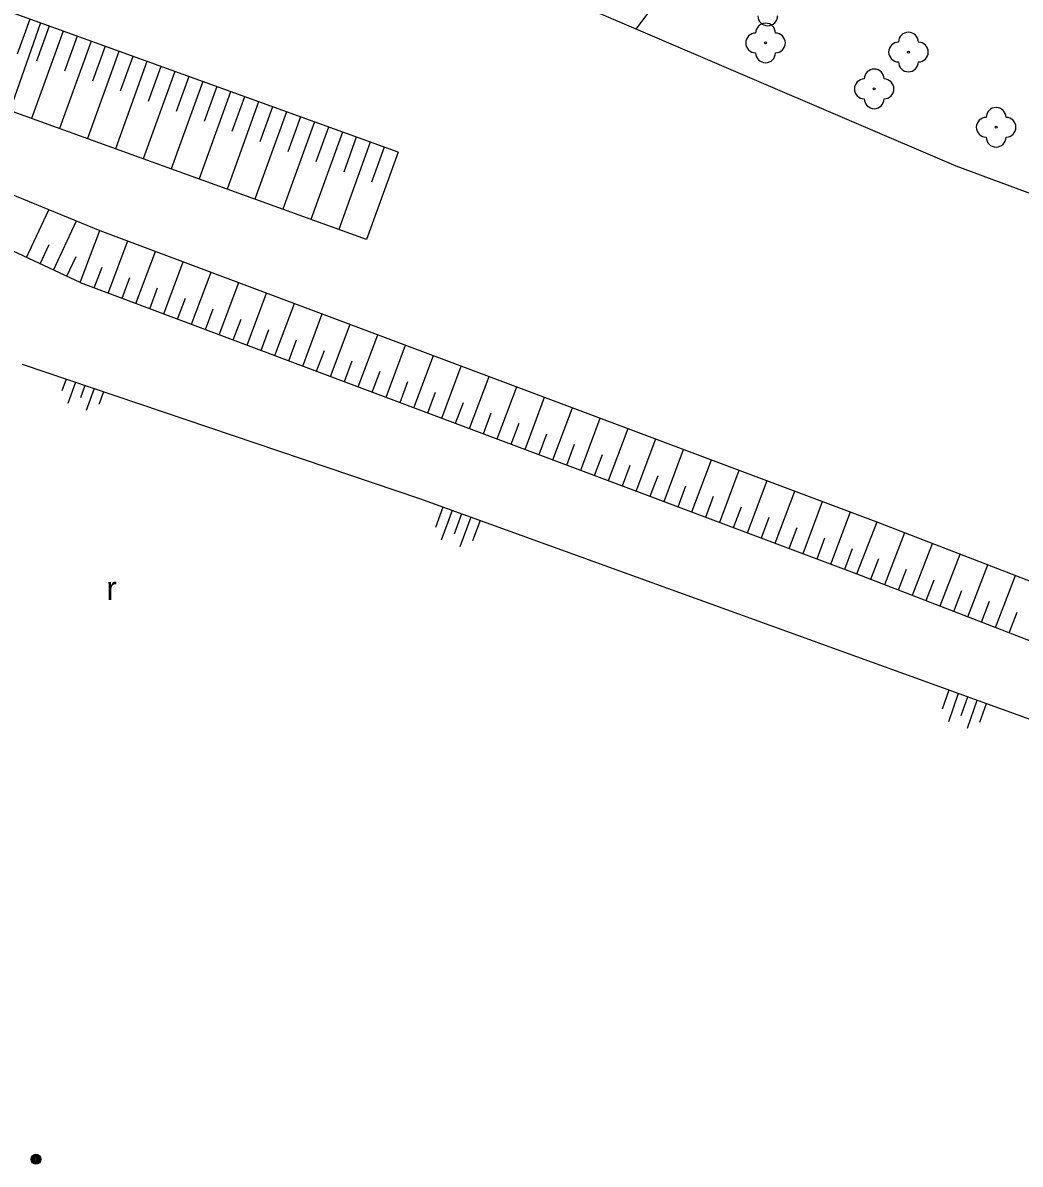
# Model space of a CAD drawing. Extents: x -539515 to -538098, y -1182060 to -1180157.
# Drawn here: x -538751.7 to -538701.3, y -1181681.4 to -1181623.8 of the extents above; entities that cross this region are included whole.
import ezdxf

# ---------------------------------------------------------------- set-up
doc = ezdxf.new("R2010")
doc.units = 0
for name, color, linetype in [('Vrstva 10', 7, 'Continuous'), ('Vrstva 14', 7, 'Continuous'), ('Vrstva 15', 7, 'Continuous'), ('Vrstva 21', 7, 'Continuous'), ('Vrstva 22', 7, 'Continuous'), ('Vrstva 25', 7, 'Continuous'), ('Vrstva 36', 7, 'Continuous'), ('Vrstva 7', 7, 'Continuous')]:
    doc.layers.add(name, color=color, linetype=linetype)

msp = doc.modelspace()

# ---------------------------------------------------------------- linework, layer by layer
at = {"layer": 'Vrstva 10'}
for p, q in [((-538731.63, -1181647.82), (-538751.71, -1181641.03)), ((-538692.82, -1181661.87), (-538731.63, -1181647.82))]:
    msp.add_line(p, q, dxfattribs=at)
at = {"layer": 'Vrstva 14'}
for p, q in [((-538750.64, -1181623.84), (-538761.845, -1181619.797)), ((-538732.73, -1181630.31), (-538750.64, -1181623.84)), ((-538746.414, -1181630.353), (-538763.53, -1181624.174)), ((-538764.77, -1181627.331), (-538747.803, -1181634.267)), ((-538748.79, -1181636.9), (-538765.465, -1181629.07)), ((-538734.323, -1181634.721), (-538746.414, -1181630.353)), ((-538747.803, -1181634.267), (-538708.591, -1181648.966)), ((-538748.79, -1181636.9), (-538709.55, -1181651.61)), ((-538708.591, -1181648.966), (-538668.703, -1181664.435)), ((-538709.55, -1181651.61), (-538669.53, -1181667.13))]:
    msp.add_line(p, q, dxfattribs=at)
at = {"layer": 'Vrstva 15'}
for p, q in [((-538750.808, -1181623.779), (-538752.356, -1181628.207)), ((-538751.345, -1181623.585), (-538751.983, -1181625.35)), ((-538750.365, -1181623.939), (-538751.002, -1181625.704)), ((-538749.659, -1181624.194), (-538751.253, -1181628.606)), ((-538748.248, -1181624.704), (-538749.842, -1181629.115)), ((-538748.954, -1181624.449), (-538749.591, -1181626.214)), ((-538746.838, -1181625.214), (-538748.431, -1181629.625)), ((-538747.543, -1181624.959), (-538748.18, -1181626.723)), ((-538745.427, -1181625.723), (-538747.02, -1181630.134)), ((-538746.132, -1181625.468), (-538746.77, -1181627.233)), ((-538744.016, -1181626.233), (-538745.61, -1181630.644)), ((-538744.722, -1181625.978), (-538745.359, -1181627.742)), ((-538742.605, -1181626.743), (-538744.199, -1181631.153)), ((-538743.311, -1181626.488), (-538743.948, -1181628.252)), ((-538741.9, -1181626.997), (-538742.537, -1181628.762)), ((-538741.195, -1181627.252), (-538742.788, -1181631.663)), ((-538740.489, -1181627.507), (-538741.127, -1181629.271)), ((-538739.784, -1181627.762), (-538741.377, -1181632.173)), ((-538739.078, -1181628.017), (-538739.716, -1181629.781)), ((-538738.373, -1181628.271), (-538739.967, -1181632.682)), ((-538737.668, -1181628.526), (-538738.305, -1181630.291)), ((-538736.962, -1181628.781), (-538738.556, -1181633.192)), ((-538735.552, -1181629.291), (-538737.145, -1181633.702)), ((-538736.257, -1181629.036), (-538736.894, -1181630.8)), ((-538734.141, -1181629.8), (-538735.734, -1181634.211)), ((-538734.846, -1181629.546), (-538735.484, -1181631.31)), ((-538732.73, -1181630.31), (-538734.323, -1181634.721)), ((-538733.435, -1181630.055), (-538734.073, -1181631.819)), ((-538751.506, -1181635.625), (-538750.374, -1181633.216)), ((-538750.148, -1181636.262), (-538748.984, -1181633.784)), ((-538748.79, -1181636.9), (-538747.803, -1181634.267)), ((-538750.827, -1181635.944), (-538750.368, -1181634.966)), ((-538747.385, -1181637.427), (-538746.398, -1181634.794)), ((-538749.469, -1181636.581), (-538748.997, -1181635.576)), ((-538745.981, -1181637.953), (-538744.994, -1181635.32)), ((-538748.088, -1181637.163), (-538747.693, -1181636.11)), ((-538744.576, -1181638.48), (-538743.589, -1181635.846)), ((-538746.683, -1181637.69), (-538746.288, -1181636.637)), ((-538743.172, -1181639.006), (-538742.185, -1181636.373)), ((-538745.279, -1181638.216), (-538744.884, -1181637.163)), ((-538741.767, -1181639.533), (-538740.78, -1181636.9)), ((-538743.874, -1181638.743), (-538743.479, -1181637.69)), ((-538740.363, -1181640.059), (-538739.376, -1181637.426)), ((-538738.958, -1181640.586), (-538737.971, -1181637.953)), ((-538742.47, -1181639.269), (-538742.075, -1181638.216)), ((-538737.554, -1181641.112), (-538736.566, -1181638.479)), ((-538741.065, -1181639.796), (-538740.67, -1181638.743)), ((-538736.149, -1181641.639), (-538735.162, -1181639.006)), ((-538739.66, -1181640.322), (-538739.266, -1181639.269)), ((-538734.744, -1181642.165), (-538733.757, -1181639.532)), ((-538738.256, -1181640.849), (-538737.861, -1181639.796)), ((-538733.34, -1181642.692), (-538732.353, -1181640.059)), ((-538736.851, -1181641.375), (-538736.456, -1181640.322)), ((-538735.447, -1181641.902), (-538735.052, -1181640.849)), ((-538731.935, -1181643.218), (-538730.948, -1181640.585)), ((-538734.042, -1181642.429), (-538733.647, -1181641.375)), ((-538730.531, -1181643.745), (-538729.544, -1181641.112)), ((-538749.509, -1181641.774), (-538749.727, -1181642.371)), ((-538749.036, -1181641.934), (-538749.428, -1181643.012)), ((-538732.638, -1181642.955), (-538732.243, -1181641.902)), ((-538729.126, -1181644.271), (-538728.139, -1181641.638)), ((-538748.562, -1181642.095), (-538748.787, -1181642.714)), ((-538748.088, -1181642.255), (-538748.489, -1181643.355)), ((-538747.614, -1181642.415), (-538747.848, -1181643.056)), ((-538731.233, -1181643.482), (-538730.838, -1181642.428)), ((-538727.722, -1181644.798), (-538726.735, -1181642.165)), ((-538729.829, -1181644.008), (-538729.434, -1181642.955)), ((-538726.317, -1181645.324), (-538725.33, -1181642.691)), ((-538728.424, -1181644.535), (-538728.029, -1181643.481)), ((-538724.913, -1181645.851), (-538723.925, -1181643.218)), ((-538727.019, -1181645.061), (-538726.625, -1181644.008)), ((-538723.508, -1181646.378), (-538722.521, -1181643.744)), ((-538722.104, -1181646.904), (-538721.116, -1181644.271)), ((-538725.615, -1181645.588), (-538725.22, -1181644.534)), ((-538720.699, -1181647.431), (-538719.712, -1181644.797)), ((-538724.21, -1181646.114), (-538723.815, -1181645.061)), ((-538719.294, -1181647.957), (-538718.307, -1181645.324)), ((-538722.806, -1181646.641), (-538722.411, -1181645.587)), ((-538717.89, -1181648.484), (-538716.903, -1181645.85)), ((-538721.401, -1181647.167), (-538721.006, -1181646.114)), ((-538716.485, -1181649.01), (-538715.498, -1181646.377)), ((-538719.997, -1181647.694), (-538719.602, -1181646.64)), ((-538718.592, -1181648.22), (-538718.197, -1181647.167)), ((-538715.081, -1181649.537), (-538714.094, -1181646.903)), ((-538717.188, -1181648.747), (-538716.793, -1181647.694)), ((-538713.676, -1181650.063), (-538712.689, -1181647.43)), ((-538730.472, -1181648.239), (-538730.849, -1181649.266)), ((-538715.783, -1181649.273), (-538715.388, -1181648.22)), ((-538712.272, -1181650.59), (-538711.284, -1181647.956)), ((-538730.004, -1181648.409), (-538730.551, -1181649.908)), ((-538729.533, -1181648.579), (-538729.91, -1181649.61)), ((-538729.062, -1181648.75), (-538729.612, -1181650.251)), ((-538728.594, -1181648.919), (-538728.97, -1181649.953)), ((-538714.378, -1181649.8), (-538713.984, -1181648.747)), ((-538710.867, -1181651.116), (-538709.88, -1181648.483)), ((-538712.974, -1181650.326), (-538712.579, -1181649.273)), ((-538709.55, -1181651.61), (-538708.533, -1181648.988)), ((-538711.569, -1181650.853), (-538711.175, -1181649.8)), ((-538708.151, -1181652.152), (-538707.135, -1181649.531)), ((-538706.753, -1181652.695), (-538705.736, -1181650.073)), ((-538710.165, -1181651.38), (-538709.77, -1181650.326)), ((-538705.354, -1181653.237), (-538704.338, -1181650.615)), ((-538708.851, -1181651.881), (-538708.444, -1181650.832)), ((-538703.956, -1181653.779), (-538702.939, -1181651.158)), ((-538707.452, -1181652.424), (-538707.045, -1181651.375)), ((-538702.557, -1181654.322), (-538701.541, -1181651.7)), ((-538706.054, -1181652.966), (-538705.647, -1181651.917)), ((-538704.655, -1181653.508), (-538704.248, -1181652.46)), ((-538703.257, -1181654.051), (-538702.85, -1181653.002)), ((-538701.858, -1181654.593), (-538701.451, -1181653.544)), ((-538704.901, -1181657.496), (-538705.239, -1181658.456)), ((-538704.432, -1181657.666), (-538704.933, -1181659.094)), ((-538703.961, -1181657.837), (-538704.296, -1181658.788)), ((-538703.491, -1181658.007), (-538703.99, -1181659.425)), ((-538703.022, -1181658.177), (-538703.352, -1181659.119))]:
    msp.add_line(p, q, dxfattribs=at)
at = {"layer": 'Vrstva 21'}
msp.add_line((-538720.709, -1181624.093), (-538717.86, -1181620.25), dxfattribs=at)
at = {"layer": 'Vrstva 22'}
for centre in [(-538714.17, -1181624.79), (-538706.95, -1181625.25), (-538708.68, -1181627.11), (-538702.52, -1181629.05)]:
    msp.add_circle(centre, 0.05, dxfattribs=at)
for centre, start, end in [((-538714.06, -1181623.42), 180, 0), ((-538714.17, -1181624.29), 0, 180), ((-538714.67, -1181624.79), 90, 270), ((-538713.67, -1181624.79), 270, 90), ((-538706.95, -1181624.75), 0, 180), ((-538707.45, -1181625.25), 90, 270), ((-538706.45, -1181625.25), 270, 90), ((-538714.17, -1181625.29), 180, 0), ((-538706.95, -1181625.75), 180, 0), ((-538708.68, -1181626.61), 0, 180), ((-538709.18, -1181627.11), 90, 270), ((-538708.18, -1181627.11), 270, 90), ((-538708.68, -1181627.61), 180, 0), ((-538702.52, -1181628.55), 0, 180), ((-538703.02, -1181629.05), 90, 270), ((-538702.02, -1181629.05), 270, 90), ((-538702.52, -1181629.55), 180, 0)]:
    msp.add_arc(centre, 0.5, start, end, dxfattribs=at)
at = {"layer": 'Vrstva 25'}
for radius in [0.25, 0.2, 0.15, 0.1, 0.05]:
    msp.add_circle((-538751.03, -1181681.19), radius, dxfattribs=at)
at = {"layer": 'Vrstva 7'}
for points in [[(-538720.709, -1181624.093), (-538722.56, -1181623.3)], [(-538704.54, -1181631.02), (-538720.709, -1181624.093)], [(-538683.065, -1181638.969), (-538704.54, -1181631.02)]]:
    msp.add_lwpolyline(points, dxfattribs=at)

# ---------------------------------------------------------------- texts
at = {"layer": 'Vrstva 36'}
msp.add_text('r', height=1.2, dxfattribs=at).set_placement((-538747.476, -1181652.94))

doc.saveas('drawing.dxf')
